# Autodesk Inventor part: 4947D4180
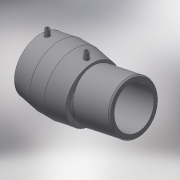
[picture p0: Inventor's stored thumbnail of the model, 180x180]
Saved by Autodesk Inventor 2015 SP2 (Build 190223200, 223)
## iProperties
Created: 2017-06
Part Number: 4947D4180
Material: Generic
Description: PLASSON ADJUSTABLE ELBOW (ONE SIDE) 180
Document SubType Name: Modeling
Designer: KIM
Mass: 3815.49 g
Surface Area: 4566.88 cm^2
Volume: 3815.49 cm^3
Density: 1 g/cm^3
Appearance: Default
Author: KIM
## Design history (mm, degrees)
derived "4947D4.ipt"
feature "Solid1::4947D4.ipt"
tag "TaggingFeature1"
body "Solid1"
other parameters: "d0" = 191.625, "d2" = 223, "d3" = 138, "d4" = 69, "d5" = 200.7, "d8" = 168 deg, "d10" = 55.2, "d11" = 18.4, "d29" = 128, "d30" = 15, "d31" = 73, "d34" = 5 deg, "d41" = 4, "d42" = 14, "d43" = 0, "d48" = 162, "d55" = 32.175, "d57" = 168 deg, "d62" = 3, "d63" = 0, "d65" = 365, "d67" = 162, "d68" = 135 deg, "d69" = 138, "d70" = 82.51, "d71" = 4.46, "L_" = 365, "L_1" = 138, "D_" = 223, "A_" = 128, "d_2" = 12, "L_0" = 148, "L_2" = 138, "d54" = 53.625, "d59" = 206.43096
